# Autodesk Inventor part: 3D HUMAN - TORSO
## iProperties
Category: PART
Company: Cross Bros.
Shininess: 64.0
Length Units: 11272
Angle Units: 11279
Time Units: 11290
Mass Units: 11286
Length Display Precision: 3
Angle Display Precision: 2
Compacted: True
Part Number: 3D HUMAN - TORSO
Document SubType Name: Modeling
Created: 2003-03
Designer: MVF
Catalog Web Link: www.crossbros.com
Density: 0.0
Volumn: 0.0
Area: 0.0
PropertySet Name: Model Information
Control State: 0
Master: False
Checked Out: False
Author: MVF
Title: iMike
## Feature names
1. Revolution1
2. Extrusion3
3. Extrusion2
4. Revolution3
5. Fillet1
6. Fillet2
